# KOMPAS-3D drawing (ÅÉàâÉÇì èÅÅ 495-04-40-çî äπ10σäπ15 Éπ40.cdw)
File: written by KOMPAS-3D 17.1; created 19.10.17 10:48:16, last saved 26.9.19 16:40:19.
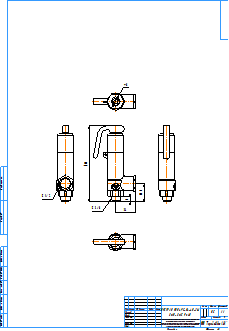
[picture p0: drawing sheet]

Sheet 1: A2, portrait

Title block, sheet 1: name: ПРЕГРАН КПП 495-04-40-ЗМ / Ду10хДу15 Ру40; material: Сталь 20  ГОСТ 1050-2013; mass: 0,5; sheets: 1; sheet format: A2; stored path: C:\Users\kka\KOMPAS_Work\!Trash\Прегран КПП 495\ПРЕГРАН КПП 495-04-40-ЗМ\KOMPAS 2D\Прегран КПП 495 Ду10хДу15 Ру40.cdw

Views: Спереди 6, Проекционный вид 7, Проекционный вид 8, Проекционный вид 9, Проекционный вид 10
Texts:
  kka
  adl
  Рама для чертежей
  Лит-Масса-Масштаб
  Материал-Предприятие
  Масштаб
  Изм.
  Лист
  № докум.
  Подп.
  Дата
  Лит.
  Разраб.
  Пров.
  Т.контр.
  Листов
  Внимание! Данный продукт является объектом авторского права ООО «Торговый Дом АДЛ».
  Запрещается изменение, копирование, распространение
  (в том числе путем копирования на другие сайты и ресурсы в Интернете)
  или любое иное использование информации и объектов без предварительного
  согласия правообладателя (ООО «Торговый Дом АДЛ»).
  Н.контр.
  Утв.
  ООО "Торговый дом АДЛ"
  Изменение
  Номер документа
  Подпись
  Обозначение документа
  Наименование изделия
  Масса изделия по ГОСТ 2.109-73
  Порядковый номер листа
  Общее количество листов в документе
  Характер работы, выполненной лицом, подписавшим документ
  Наименование или индекс предприятия, выпускающего документ
  Инв. № подл.
  Подп. и дата
  Взам. инв. №
  Инв. № дубл.
  Инвентарный номер подлинника по ГОСТ 2.501-68
  Подпись принявшего подлинник в отдел технической документации
  Инвентарный номер подлинника, взамен которого выпущен данный подлинник
  Инвентарный номер дубликата по ГОСТ 2.502-68
  Подпись принявшего дубликат в отдел технической документации
  Справ. №
  Перв. примен.
  Обозначение документа, взамен или на основании которого выпущен данный документ
  Обозначение документа, в котором впервые записан данный документ
  Подпись лица, копировавшего чертеж
  Обозначение формата листа
  !Рама для чертежа
Dimensions and other numbers on the sheet: 32,5; 9; 36; 136; 8; 0,5; 1:1; 1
